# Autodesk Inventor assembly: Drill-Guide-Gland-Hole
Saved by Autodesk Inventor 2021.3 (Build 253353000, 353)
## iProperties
Created: 2023-07
Part Number: Drill-Guide-Gland-Hole
Document SubType Name: Assembly
Designer: AdminForWorker
Title: Drill-Guide-Gland-Hole v2
Author: AdminForWorker
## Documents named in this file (2)
- c:\worker\convert-fusion-r03-cosv3\tmp\job-1\7\output\files\ed1a9385-d3ff-40e3-bd37-0ed800457cac\Drill-Guide-Gland-Hole v2.iam
- c:\worker\convert-fusion-r03-cosv3\tmp\job-1\7\output\files\ed1a9385-d3ff-40e3-bd37-0ed800457cac\Gland-Hole.ipt
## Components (1 placed, 1 different names)
1. Gland-Hole:1
